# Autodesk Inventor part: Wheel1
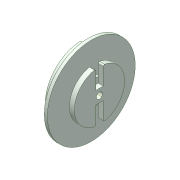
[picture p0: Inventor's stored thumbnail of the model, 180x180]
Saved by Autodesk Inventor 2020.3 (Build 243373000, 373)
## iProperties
Created: 2010-08
Part Number: Wheel1
Document SubType Name: Modeling
Designer: nguyenducthang
Density: 1 g/cm^3
Mass: 148.162 g
Surface Area: 591.857 cm^2
Volume: 148.162 cm^3
Material: Generico
Appearance: Green Pastel
Author: nguyenducthang
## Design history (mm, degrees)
node "Annotazioni"
  node "Quota diametro 1" dims "d454" = 70, "d458" = 5, "d459" = 5, "d559" = 20, "d560" = 40, "d561" = 8, "d578" = 140 (derived)
  node "Quota lineare 1" dims "d454" = 70, "d458" = 5, "d459" = 5, "d559" = 20, "d560" = 40, "d561" = 8, "d582" = 8 (derived)
  node "Quota diametro 3" dims "d454" = 70, "d458" = 5, "d459" = 5, "d559" = 20, "d560" = 40, "d561" = 8, "d591" = 40 (derived)
  node "Quota radiale 2" dims "d454" = 70, "d458" = 5, "d459" = 5, "d559" = 20, "d560" = 40, "d561" = 8, "d595" = 20 (derived)
  node "Quota lineare 5" dims "d454" = 70, "d458" = 5, "d459" = 5, "d559" = 20, "d560" = 40, "d561" = 8, "d598" = 12.2 (derived)
  node "Quota lineare 6" dims "d454" = 70, "d458" = 5, "d459" = 5, "d559" = 20, "d560" = 40, "d561" = 8, "d599" = 5 (derived)
  node "Quota radiale 3" dims "d454" = 70, "d458" = 5, "d459" = 5, "d559" = 20, "d560" = 40, "d561" = 8, "d601" = 40 (derived)
  node "Quota lineare 7" dims "d454" = 70, "d458" = 5, "d459" = 5, "d559" = 20, "d560" = 40, "d561" = 8, "d606" = 10 (derived)
  node "Quota radiale 4" dims "d454" = 70, "d458" = 5, "d459" = 5, "d559" = 20, "d560" = 40, "d561" = 8, "d608" = 5 (derived)
  node "Quota lineare 9" dims "d454" = 70, "d458" = 5, "d459" = 5, "d559" = 20, "d560" = 40, "d561" = 8, "d610" = 5 (derived)
  node "Quota lineare 10" dims "d454" = 70, "d458" = 5, "d459" = 5, "d559" = 20, "d560" = 40, "d561" = 8, "d611" = 8 (derived)
  node "Quota lineare 11" dims "d454" = 70, "d458" = 5, "d459" = 5, "d559" = 20, "d560" = 40, "d561" = 8, "d614" = 5 (derived)
  node "Quota lineare 12" dims "d454" = 70, "d458" = 5, "d459" = 5, "d559" = 20, "d560" = 40, "d561" = 8, "d615" = 10 (derived)
  node "Quota diametro 4" dims "d454" = 70, "d458" = 5, "d459" = 5, "d559" = 20, "d560" = 40, "d561" = 8, "d633" = 10 (derived)
  node "Quota radiale 7" dims "d454" = 70, "d458" = 5, "d459" = 5, "d559" = 20, "d560" = 40, "d561" = 8, "d637" = 40 (derived)
  node "Quota radiale 8" dims "d454" = 70, "d458" = 5, "d459" = 5, "d559" = 20, "d560" = 40, "d561" = 8, "d639" = 20 (derived)
  node "Quota lineare 13" dims "d454" = 70, "d458" = 5, "d459" = 5, "d559" = 20, "d560" = 40, "d561" = 8, "d642" = 12 (derived)
  node "Quota lineare 14" dims "d454" = 70, "d458" = 5, "d459" = 5, "d559" = 20, "d560" = 40, "d561" = 8, "d643" = 8 (derived)
  node "Quota radiale 9" dims "d454" = 70, "d458" = 5, "d459" = 5, "d559" = 20, "d560" = 40, "d561" = 8, "d645" = 70 (derived)
  node "Quota lineare 15" dims "d454" = 70, "d458" = 5, "d459" = 5, "d559" = 20, "d560" = 40, "d561" = 8, "d646" = 1.96742 (derived)
  node "Quota lineare 16" dims "d454" = 70, "d458" = 5, "d459" = 5, "d559" = 20, "d560" = 40, "d561" = 8, "d647" = 1.65103 (derived)
  node "Quota lineare 17" dims "d454" = 70, "d458" = 5, "d459" = 5, "d559" = 20, "d560" = 40, "d561" = 8, "d650" = 20 (derived)
revolve "Revolution7" stored, may be unused: angle "d462" = 90 deg
sketch "Sketch78"
  geometry: L1 (0, 70)-(5, 70) reference; L2 (0, -70)-(0, 70) reference; L3 (0, 8)-(-12.2, 8); L4 (0, 12)-(0, 8); L5 (0, 0)-(-29.088, 0); L6 (-12.2, 8)-(-12.2, 12); L7 (-12.2, 12)-(0, 12)
  constraints: 10 end point, 2 perpendicular, 1 collinear, 1 midpoint, 1 point on line
  dimensions: "d556" = 8 distance between parallel lines of L3 L5; "d557" = 4 distance of L3.end L6.end; "d558" = 12.2 distance of L6.end L4.start
coil "Coil9" sketch "Sketch78" pitch "d536" = 16; turns "d538" = 3; dims "d537" = 10, "d539" = 0, angle "d540" = 90 deg, angle "d541" = 90 deg, "d542" = 0, "d543" = 0
sketch "Sketch81"
  geometry: L1 (-6, 10)-(6, 10); L2 (6, 10)-(6, 50); L3 (6, 50)-(-6, 50); L4 (-6, 50)-(-6, 10); C1 r 40 at (0, 0) reference
  constraints: 8 end point, 2 parallel, 1 horizontal, 1 perpendicular
  dimensions: "d562" = 12 distance of L2.end L3.end; "d563" = 6 distance from line of L2 C1.centre; "d564" = 10 distance from line of L1 C1.centre; "d570" = 40 distance of L1.end L2.end
extrude "Extrusion65" cut sketch "Sketch81" stored distance "d565" = 10; taper "d566" = 0 deg
pattern_circular "Circular Pattern6" dims angle "d568" = 360 deg
chamfer "Chamfer24" distance "d571" = 2; stored, may be unused: second distance "d572" = 2, angle "d573" = 45 deg
sketch "Sketch83"
  geometry: C1 r 5 at (6, -10); A1 r 40 centre (6, -10) between (13.967, -49.198) and (13.967, 29.198) reference
  constraints: 1 centre point, 1 coincident
  dimensions: "d574" = 10 diameter of C1
extrude "Extrusion66" cut sketch "Sketch83" distance "d575" = 10; taper "d576" = 0 deg
node "Asse di lavoro2"
node "Solido1"
node "Corpi solidi"
node "Corpi di superficie"
sketch "Sketch69"
  geometry: L1 (0, 0)-(0, 70); L2 (0, 70)-(5, 70); L3 (5, 70)-(5, 20); L4 (5, 20)-(10, 20); L5 (18, 0)-(0, 0); L6 (10, 20)-(10, 40); L7 (10, 40)-(18, 40); L8 (18, 40)-(18, 0)
  constraints: 16 end point, 4 parallel, 3 perpendicular, 1 vertical, 1 other
  dimensions: "d454" = 70 distance of L1.start L1.end; "d458" = 5 distance of L1.end L2.end; "d459" = 5 distance of L3.end L4.end; "d559" = 20 distance between parallel lines of L4 L5; "d560" = 40 distance of L7.end L5.start; "d561" = 8 distance of L6.end L7.end
other parameters: "d489" = 6.19982 (derived), "d577" = 14.62927 (derived), "d581" = 5.16699 (derived), "d590" = 10.42062 (derived), "d594" = 6.07037 (derived), "d596" = 3.73477 (derived), "d597" = 1.56863 (derived), "d600" = -29.41066 (derived), "d604" = 6.97875 (derived), "d605" = 6.86847 (derived), "d607" = 29.622 (derived), "d612" = 0.46349 (derived), "d613" = 5.02876 (derived), "d632" = 10.10526 (derived), "d636" = 5.34376 (derived), "d638" = 0.95416 (derived), "d640" = 0 (derived), "d644" = 11.73265 (derived), "d648" = 4.37296 (derived), "d649" = 4.7183 (derived)
